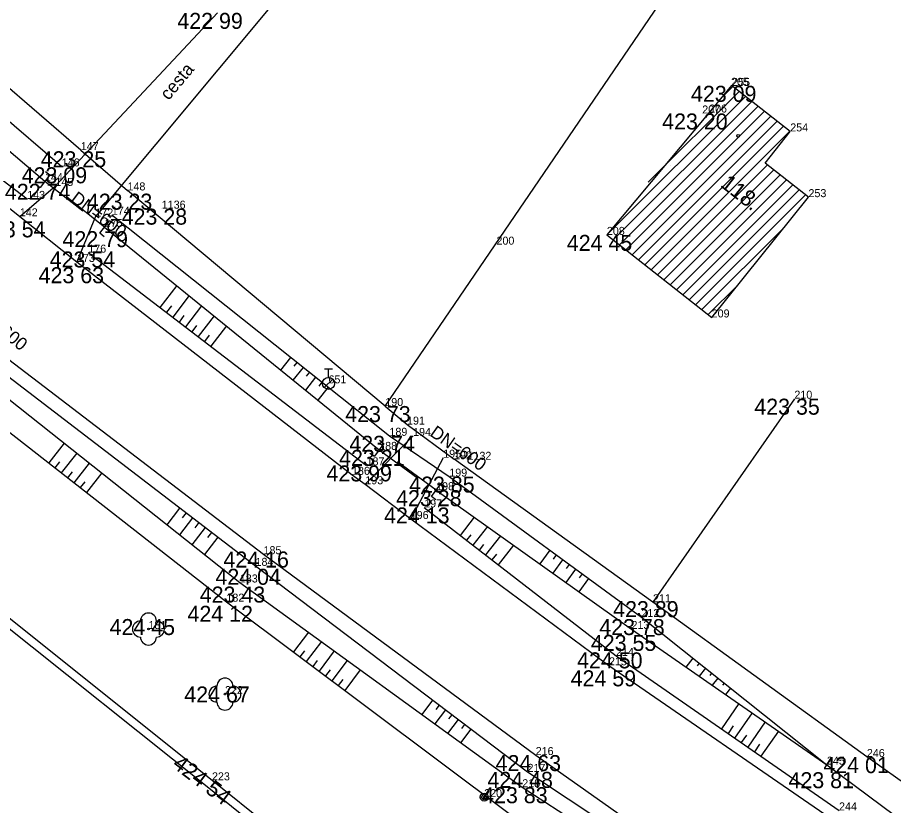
# Model space of a CAD drawing. Extents: x -559180 to -551373, y -1076947 to -1072071.
# Drawn here: x -554542.6 to -554487.8, y -1073678.4 to -1073629.1 of the extents above; entities that cross this region are included whole.
import ezdxf

# ---------------------------------------------------------------- set-up
doc = ezdxf.new("R2010")
doc.units = 0
for name, color, linetype in [('12_PLOTY', 7, 'Continuous'), ('14_BUDOVY', 7, 'Continuous'), ('17_KOMUNIKACE', 7, 'Continuous'), ('1_VODA_ZN', 7, 'Continuous'), ('20_EL_ZN', 7, 'Continuous'), ('26_SRAFY', 7, 'Continuous'), ('27_HRANA_PATA', 7, 'Continuous'), ('32', 7, 'Continuous'), ('34_ZELEN', 7, 'Continuous'), ('3_BODY', 7, 'Continuous'), ('40_KANAL_ZN', 7, 'Continuous'), ('47_ZN_STAV_OBJ$', 7, 'Continuous'), ('49_POPIS_KANAL', 7, 'Continuous'), ('52_POPIS_UCELOVY', 7, 'Continuous'), ('54_C_POPISNA', 7, 'Continuous'), ('6_VYSKY', 7, 'Continuous')]:
    doc.layers.add(name, color=color, linetype=linetype)

# ---------------------------------------------------------------- blocks, each defined once
blk = doc.blocks.new('POINT_DISPLAY')
blk.add_line((0, 0), (0, 0))
blk = doc.blocks.new('BZ')
at = {"layer": '47_ZN_STAV_OBJ$'}
blk.add_circle((0, 0), 0.0875, dxfattribs=at)
blk = doc.blocks.new('JS600')
at = {"layer": '49_POPIS_KANAL'}
blk.add_text('DN=600', height=0.8, rotation=0, dxfattribs=at).set_placement((0.752, -0.172))
blk = doc.blocks.new('STL')
at = {"layer": '34_ZELEN'}
blk.add_circle((0, 0), 0.05, dxfattribs=at)
for centre, start, end in [((0, 0.5), 0, 180), ((-0.5, 0), 90, 270), ((0.5, 0), 270, 90), ((0, -0.5), 180, 0)]:
    blk.add_arc(centre, 0.5, start, end, dxfattribs=at)
blk = doc.blocks.new('SLB')
at = {"layer": '20_EL_ZN'}
for radius in [0.25, 0.158, 0.05]:
    blk.add_circle((0, 0), radius, dxfattribs=at)
blk = doc.blocks.new('VYUST')
at = {"layer": '40_KANAL_ZN'}
for p, q in [((-0.35, 0.5), (0, 0.5)), ((0, 0.5), (0, -0.5)), ((0, 0), (3, 0.001)), ((-0.35, -0.5), (0, -0.5))]:
    blk.add_line(p, q, dxfattribs=at)
blk = doc.blocks.new('HYP')
at = {"layer": '1_VODA_ZN'}
for p, q in [((-0.25, 0.9), (0.25, 0.9)), ((0, 0.375), (0, 0.9)), ((-0.265, -0.265), (0.265, 0.265))]:
    blk.add_line(p, q, dxfattribs=at)
blk.add_circle((0, 0), 0.375, dxfattribs=at)

msp = doc.modelspace()

# ---------------------------------------------------------------- linework, layer by layer
at = {"layer": '12_PLOTY'}
for p, q in [((-554538.64, -1073637.43), (-554551.66, -1073626.19)), ((-554519.61, -1073653.43), (-554502.05, -1073627.66)), ((-554538.64, -1073637.43), (-554535.72, -1073639.95)), ((-554519.61, -1073653.43), (-554535.72, -1073639.95)), ((-554494.04, -1073652.97), (-554502.88, -1073665.7)), ((-554519.61, -1073653.43), (-554518.25, -1073654.59)), ((-554518.25, -1073654.59), (-554515.31, -1073656.76)), ((-554502.88, -1073665.7), (-554515.31, -1073656.76)), ((-554547.942, -1073663.49), (-554530.752, -1073677.22)), ((-554530.44, -1073676.83), (-554547.63, -1073663.1)), ((-554489.51, -1073675.37), (-554502.88, -1073665.7)), ((-554479.77, -1073682.26), (-554489.51, -1073675.37)), ((-554530.752, -1073677.22), (-554503.842, -1073698.76)), ((-554503.53, -1073698.37), (-554530.44, -1073676.83))]:
    msp.add_line(p, q, dxfattribs=at)
at = {"layer": '14_BUDOVY'}
for p, q in [((-554497.978, -1073633.383), (-554499.37, -1073635.08)), ((-554494.3, -1073636.26), (-554497.978, -1073633.383)), ((-554499.37, -1073635.08), (-554505.76, -1073642.73)), ((-554495.862, -1073638.256), (-554494.3, -1073636.26)), ((-554493.16, -1073640.37), (-554495.862, -1073638.256)), ((-554499.21, -1073647.89), (-554493.16, -1073640.37)), ((-554505.76, -1073642.73), (-554499.21, -1073647.89))]:
    msp.add_line(p, q, dxfattribs=at)
at = {"layer": '17_KOMUNIKACE'}
for p, q in [((-554525.78, -1073627.26), (-554537.73, -1073641.58)), ((-554540.23, -1073639.67), (-554530.1, -1073628.85)), ((-554556.69, -1073630.21), (-554542.45, -1073641.57)), ((-554542.45, -1073641.57), (-554540.23, -1073639.67)), ((-554542.45, -1073641.57), (-554538.88, -1073644.42)), ((-554537.73, -1073641.58), (-554538.88, -1073644.42)), ((-554538.88, -1073644.42), (-554521.69, -1073657.73)), ((-554544.29, -1073649.64), (-554527.22, -1073662.69)), ((-554520.86, -1073658.32), (-554517.87, -1073655.3)), ((-554515.99, -1073656.66), (-554518.02, -1073660.49)), ((-554521.69, -1073657.73), (-554520.86, -1073658.32)), ((-554520.86, -1073658.32), (-554518.02, -1073660.49)), ((-554518.02, -1073660.49), (-554505.63, -1073669.64)), ((-554527.22, -1073662.69), (-554510.21, -1073675.25)), ((-554505.63, -1073669.64), (-554491.54, -1073679.37)), ((-554510.21, -1073675.25), (-554496.41, -1073684.98))]:
    msp.add_line(p, q, dxfattribs=at)
at = {"layer": '26_SRAFY'}
for p, q in [((-554532.645, -1073645.898), (-554533.691, -1073647.266)), ((-554531.868, -1073646.528), (-554532.897, -1073647.873)), ((-554532.982, -1073647.162), (-554533.294, -1073647.569)), ((-554531.091, -1073647.159), (-554532.102, -1073648.481)), ((-554532.193, -1073647.777), (-554532.499, -1073648.177)), ((-554530.315, -1073647.789), (-554531.308, -1073649.088)), ((-554531.404, -1073648.391), (-554531.705, -1073648.784)), ((-554529.538, -1073648.42), (-554530.514, -1073649.696)), ((-554530.615, -1073649.006), (-554530.911, -1073649.392)), ((-554526.137, -1073651.18), (-554525.505, -1073650.387)), ((-554525.305, -1073650.937), (-554525.114, -1073650.698)), ((-554525.361, -1073651.81), (-554524.723, -1073651.01)), ((-554524.524, -1073651.563), (-554524.332, -1073651.322)), ((-554524.584, -1073652.441), (-554523.941, -1073651.633)), ((-554523.744, -1073652.188), (-554523.55, -1073651.945)), ((-554523.808, -1073653.071), (-554523.159, -1073652.256)), ((-554539.678, -1073655.749), (-554540.647, -1073656.99)), ((-554538.895, -1073656.371), (-554539.858, -1073657.605)), ((-554539.963, -1073656.926), (-554540.253, -1073657.298)), ((-554538.111, -1073656.992), (-554539.07, -1073658.221)), ((-554539.176, -1073657.543), (-554539.464, -1073657.913)), ((-554537.328, -1073657.614), (-554538.282, -1073658.836)), ((-554538.389, -1073658.161), (-554538.676, -1073658.528)), ((-554533.243, -1073660.855), (-554532.442, -1073659.807)), ((-554532.287, -1073660.427), (-554532.044, -1073660.111)), ((-554532.46, -1073661.476), (-554531.647, -1073660.415)), ((-554531.496, -1073661.039), (-554531.25, -1073660.719)), ((-554514.046, -1073660.385), (-554514.922, -1073661.517)), ((-554531.676, -1073662.098), (-554530.853, -1073661.022)), ((-554530.705, -1073661.651), (-554530.456, -1073661.326)), ((-554513.23, -1073660.965), (-554514.132, -1073662.129)), ((-554530.893, -1073662.72), (-554530.059, -1073661.63)), ((-554514.26, -1073661.479), (-554514.527, -1073661.823)), ((-554512.415, -1073661.545), (-554513.341, -1073662.742)), ((-554513.462, -1073662.081), (-554513.736, -1073662.435)), ((-554511.599, -1073662.125), (-554512.55, -1073663.354)), ((-554512.664, -1073662.684), (-554512.945, -1073663.048)), ((-554509.94, -1073663.304), (-554509.311, -1073662.445)), ((-554509.095, -1073662.996), (-554508.908, -1073662.74)), ((-554509.124, -1073663.883), (-554508.504, -1073663.035)), ((-554508.285, -1073663.583), (-554508.1, -1073663.33)), ((-554508.309, -1073664.463), (-554507.697, -1073663.625)), ((-554507.476, -1073664.17), (-554507.293, -1073663.92)), ((-554507.494, -1073665.042), (-554506.89, -1073664.215)), ((-554524.417, -1073667.566), (-554525.346, -1073668.805)), ((-554523.607, -1073668.154), (-554524.545, -1073669.405)), ((-554524.665, -1073668.732), (-554524.945, -1073669.105)), ((-554522.797, -1073668.741), (-554523.745, -1073670.005)), ((-554523.862, -1073669.328), (-554524.145, -1073669.705)), ((-554521.988, -1073669.328), (-554522.945, -1073670.605)), ((-554500.801, -1073669.744), (-554500.365, -1073669.196)), ((-554500.099, -1073669.664), (-554499.974, -1073669.508)), ((-554523.06, -1073669.924), (-554523.345, -1073670.305)), ((-554521.178, -1073669.915), (-554522.145, -1073671.205)), ((-554499.978, -1073670.316), (-554499.583, -1073669.819)), ((-554522.257, -1073670.52), (-554522.545, -1073670.905)), ((-554499.304, -1073670.272), (-554499.192, -1073670.131)), ((-554499.155, -1073670.887), (-554498.801, -1073670.442)), ((-554498.51, -1073670.88), (-554498.409, -1073670.754)), ((-554498.332, -1073671.459), (-554498.018, -1073671.065)), ((-554517.31, -1073672.72), (-554516.63, -1073671.822)), ((-554516.434, -1073672.391), (-554516.232, -1073672.124)), ((-554497.504, -1073672.034), (-554498.6, -1073673.617)), ((-554516.501, -1073673.307), (-554515.833, -1073672.426)), ((-554515.633, -1073672.99), (-554515.435, -1073672.728)), ((-554496.683, -1073672.605), (-554497.778, -1073674.186)), ((-554515.691, -1073673.894), (-554515.036, -1073673.03)), ((-554514.832, -1073673.589), (-554514.638, -1073673.332)), ((-554495.861, -1073673.175), (-554496.956, -1073674.756)), ((-554514.881, -1073674.481), (-554514.239, -1073673.634)), ((-554497.86, -1073673.427), (-554498.189, -1073673.901)), ((-554495.04, -1073673.746), (-554496.134, -1073675.325)), ((-554497.039, -1073673.997), (-554497.367, -1073674.471)), ((-554496.217, -1073674.567), (-554496.545, -1073675.04))]:
    msp.add_line(p, q, dxfattribs=at)
at = {"layer": '27_HRANA_PATA'}
for p, q in [((-554553.84, -1073626.4), (-554539.83, -1073638.45)), ((-554554.76, -1073627.66), (-554540.88, -1073639.37)), ((-554556.17, -1073629.65), (-554541.99, -1073640.48)), ((-554536.7, -1073641.47), (-554519.35, -1073655.29)), ((-554537.15, -1073642.24), (-554519.99, -1073656.17)), ((-554538.17, -1073643.84), (-554520.78, -1073657.14)), ((-554545.43, -1073649.868), (-554527.72, -1073663.42)), ((-554545.75, -1073650.93), (-554528.7, -1073664.46)), ((-554547.25, -1073651.835), (-554529.54, -1073665.66)), ((-554519.35, -1073655.29), (-554515.61, -1073657.84)), ((-554515.61, -1073657.84), (-554503.6, -1073666.62)), ((-554516.43, -1073658.69), (-554504.22, -1073667.37)), ((-554517.18, -1073659.77), (-554505.19, -1073669.05)), ((-554527.72, -1073663.42), (-554510.72, -1073676.3)), ((-554528.7, -1073664.46), (-554511.05, -1073677.26)), ((-554529.54, -1073665.66), (-554511.79, -1073678.97)), ((-554503.6, -1073666.62), (-554492.01, -1073675.85)), ((-554504.22, -1073667.37), (-554492.01, -1073675.85)), ((-554505.19, -1073669.05), (-554491.25, -1073678.71)), ((-554492.01, -1073675.85), (-554482.51, -1073682.92)), ((-554510.72, -1073676.3), (-554496.84, -1073685.47)), ((-554511.05, -1073677.26), (-554497.4, -1073686.05))]:
    msp.add_line(p, q, dxfattribs=at)
at = {"layer": '32'}
for p, q in [((-554503.175, -1073639.437), (-554497.497, -1073633.76)), ((-554498.666, -1073634.222), (-554497.894, -1073633.449)), ((-554505.76, -1073642.73), (-554497.1, -1073634.07)), ((-554505.364, -1073643.042), (-554496.703, -1073634.38)), ((-554504.969, -1073643.353), (-554496.306, -1073634.69)), ((-554504.573, -1073643.665), (-554495.909, -1073635.001)), ((-554504.178, -1073643.976), (-554495.513, -1073635.311)), ((-554503.782, -1073644.288), (-554495.116, -1073635.621)), ((-554503.387, -1073644.6), (-554494.719, -1073635.932)), ((-554502.991, -1073644.911), (-554494.323, -1073636.242)), ((-554502.596, -1073645.223), (-554495.731, -1073638.358)), ((-554502.2, -1073645.534), (-554495.335, -1073638.669)), ((-554501.805, -1073645.846), (-554494.938, -1073638.979)), ((-554501.409, -1073646.157), (-554494.541, -1073639.289)), ((-554501.014, -1073646.469), (-554494.144, -1073639.6)), ((-554500.618, -1073646.781), (-554493.748, -1073639.91)), ((-554500.223, -1073647.092), (-554493.351, -1073640.221)), ((-554499.827, -1073647.404), (-554494.669, -1073642.245)), ((-554499.432, -1073647.715), (-554497.579, -1073645.863))]:
    msp.add_line(p, q, dxfattribs=at)

# ---------------------------------------------------------------- block references
at = {"layer": '1_VODA_ZN'}
for name, p in [('POINT_DISPLAY', (-554498, -1073633.41)), ('POINT_DISPLAY', (-554497.93, -1073633.42)), ('POINT_DISPLAY', (-554499.8, -1073635.14)), ('POINT_DISPLAY', (-554499.37, -1073635.08)), ('POINT_DISPLAY', (-554494.3, -1073636.26)), ('POINT_DISPLAY', (-554538.64, -1073637.43)), ('POINT_DISPLAY', (-554539.83, -1073638.45)), ('POINT_DISPLAY', (-554540.88, -1073639.37)), ('POINT_DISPLAY', (-554540.23, -1073639.67)), ('POINT_DISPLAY', (-554535.72, -1073639.95)), ('POINT_DISPLAY', (-554541.99, -1073640.48)), ('POINT_DISPLAY', (-554493.16, -1073640.37)), ('POINT_DISPLAY', (-554533.58, -1073641.09)), ('POINT_DISPLAY', (-554542.45, -1073641.57)), ('POINT_DISPLAY', (-554537.73, -1073641.58)), ('POINT_DISPLAY', (-554536.7, -1073641.47)), ('POINT_DISPLAY', (-554537.15, -1073642.24)), ('POINT_DISPLAY', (-554505.76, -1073642.73)), ('POINT_DISPLAY', (-554512.66, -1073643.34)), ('POINT_DISPLAY', (-554538.17, -1073643.84)), ('POINT_DISPLAY', (-554538.88, -1073644.42)), ('POINT_DISPLAY', (-554499.21, -1073647.89)), ('HYP', (-554523.16, -1073652.01)), ('POINT_DISPLAY', (-554523.16, -1073652.01)), ('POINT_DISPLAY', (-554494.04, -1073652.97)), ('POINT_DISPLAY', (-554519.61, -1073653.43)), ('POINT_DISPLAY', (-554518.25, -1073654.59)), ('POINT_DISPLAY', (-554519.35, -1073655.29)), ('POINT_DISPLAY', (-554517.87, -1073655.3)), ('POINT_DISPLAY', (-554519.99, -1073656.17)), ('POINT_DISPLAY', (-554515.99, -1073656.66)), ('POINT_DISPLAY', (-554515.31, -1073656.76)), ('POINT_DISPLAY', (-554514.47, -1073656.79)), ('POINT_DISPLAY', (-554520.78, -1073657.14)), ('POINT_DISPLAY', (-554521.69, -1073657.73)), ('POINT_DISPLAY', (-554515.61, -1073657.84)), ('POINT_DISPLAY', (-554520.86, -1073658.32)), ('POINT_DISPLAY', (-554516.43, -1073658.69)), ('POINT_DISPLAY', (-554517.18, -1073659.77)), ('POINT_DISPLAY', (-554518.02, -1073660.49)), ('POINT_DISPLAY', (-554527.22, -1073662.69)), ('POINT_DISPLAY', (-554527.72, -1073663.42)), ('POINT_DISPLAY', (-554528.7, -1073664.46)), ('POINT_DISPLAY', (-554529.54, -1073665.66)), ('POINT_DISPLAY', (-554502.88, -1073665.7)), ('POINT_DISPLAY', (-554503.6, -1073666.62)), ('POINT_DISPLAY', (-554534.41, -1073667.37)), ('POINT_DISPLAY', (-554504.22, -1073667.37)), ('POINT_DISPLAY', (-554505.19, -1073669.05)), ('POINT_DISPLAY', (-554505.63, -1073669.64)), ('POINT_DISPLAY', (-554529.63, -1073671.44)), ('POINT_DISPLAY', (-554510.21, -1073675.25)), ('POINT_DISPLAY', (-554489.51, -1073675.37)), ('POINT_DISPLAY', (-554492.01, -1073675.85)), ('POINT_DISPLAY', (-554510.72, -1073676.3)), ('POINT_DISPLAY', (-554530.44, -1073676.83)), ('POINT_DISPLAY', (-554511.05, -1073677.26)), ('POINT_DISPLAY', (-554513.43, -1073677.88))]:
    msp.add_blockref(name, p, dxfattribs=at)
at = {"layer": '20_EL_ZN'}
msp.add_blockref('SLB', (-554513.43, -1073677.88), dxfattribs=at)
at = {"layer": '32'}
for p in [(-554501.815, -1073638.385), (-554505.76, -1073642.73)]:
    msp.add_blockref('POINT_DISPLAY', p, dxfattribs=at)
at = {"layer": '34_ZELEN'}
for p in [(-554534.41, -1073667.37), (-554529.63, -1073671.44)]:
    msp.add_blockref('STL', p, dxfattribs=at)
at = {"layer": '40_KANAL_ZN'}
for p, xscale, yscale, rotation in [((-554540.88, -1073639.37), 0.999999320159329, 0.9999993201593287, -38.11928391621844), ((-554537.15, -1073642.24), 1.0000001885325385, 1.0000001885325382, 141.65216076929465), ((-554519.99, -1073656.17), 0.9999985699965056, 0.9999985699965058, -36.17282544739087), ((-554516.43, -1073658.69), 1.0000023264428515, 1.0000023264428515, 143.7866682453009)]:
    msp.add_blockref('VYUST', p, dxfattribs=dict(at, xscale=xscale, yscale=yscale, rotation=rotation))
at = {"layer": '47_ZN_STAV_OBJ$'}
msp.add_blockref('BZ', (-554497.553, -1073636.538), dxfattribs=at)
at = {"layer": '49_POPIS_KANAL'}
for p, xscale, yscale, rotation in [((-554539.829, -1073640.008), 1.0000022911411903, 1.0000022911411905, -36.81685698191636), ((-554545.927, -1073646.917), 0.9999989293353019, 0.9999989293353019, -39.193498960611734), ((-554517.396, -1073654.669), 0.9999979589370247, 0.9999979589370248, -35.32795063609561)]:
    msp.add_blockref('JS600', p, dxfattribs=dict(at, xscale=xscale, yscale=yscale, rotation=rotation))

# ---------------------------------------------------------------- texts
at = {"layer": '3_BODY'}
for s, p in [('205', (-554498, -1073633.41)), ('255', (-554497.93, -1073633.42)), ('207', (-554499.8, -1073635.14)), ('206', (-554499.37, -1073635.08)), ('254', (-554494.3, -1073636.26)), ('147', (-554538.64, -1073637.43)), ('146', (-554539.83, -1073638.45)), ('144', (-554540.88, -1073639.37)), ('145', (-554540.23, -1073639.67)), ('148', (-554535.72, -1073639.95)), ('143', (-554541.99, -1073640.48)), ('253', (-554493.16, -1073640.37)), ('142', (-554542.45, -1073641.57)), ('172', (-554537.73, -1073641.58)), ('174', (-554536.7, -1073641.47)), ('1136', (-554533.58, -1073641.09)), ('175', (-554537.15, -1073642.24)), ('208', (-554505.76, -1073642.73)), ('200', (-554512.66, -1073643.34)), ('176', (-554538.17, -1073643.84)), ('173', (-554538.88, -1073644.42)), ('209', (-554499.21, -1073647.89)), ('651', (-554523.16, -1073652.01)), ('210', (-554494.04, -1073652.97)), ('190', (-554519.61, -1073653.43)), ('191', (-554518.25, -1073654.59)), ('189', (-554519.35, -1073655.29)), ('194', (-554517.87, -1073655.3)), ('188', (-554519.99, -1073656.17)), ('195', (-554515.99, -1073656.66)), ('192', (-554515.31, -1073656.76)), ('1132', (-554514.47, -1073656.79)), ('187', (-554520.78, -1073657.14)), ('186', (-554521.69, -1073657.73)), ('199', (-554515.61, -1073657.84)), ('193', (-554520.86, -1073658.32)), ('198', (-554516.43, -1073658.69)), ('197', (-554517.18, -1073659.77)), ('196', (-554518.02, -1073660.49)), ('185', (-554527.22, -1073662.69)), ('184', (-554527.72, -1073663.42)), ('183', (-554528.7, -1073664.46)), ('182', (-554529.54, -1073665.66)), ('211', (-554502.88, -1073665.7)), ('212', (-554503.6, -1073666.62)), ('181', (-554534.41, -1073667.37)), ('213', (-554504.22, -1073667.37)), ('214', (-554505.19, -1073669.05)), ('215', (-554505.63, -1073669.64)), ('222', (-554529.63, -1073671.44)), ('216', (-554510.21, -1073675.25)), ('246', (-554489.51, -1073675.37)), ('245', (-554492.01, -1073675.85)), ('217', (-554510.72, -1073676.3)), ('223', (-554530.44, -1073676.83)), ('218', (-554511.05, -1073677.26)), ('220', (-554513.43, -1073677.88)), ('244', (-554491.25, -1073678.71))]:
    msp.add_text(s, height=0.5, dxfattribs=at).set_placement(p)
at = {"layer": '52_POPIS_UCELOVY'}
msp.add_text('cesta', height=0.8, rotation=50.1551, dxfattribs=at).set_placement((-554533.15, -1073634.361))
at = {"layer": '54_C_POPISNA'}
msp.add_text('118.', height=1, rotation=321.9615, dxfattribs=at).set_placement((-554498.722, -1073639.669))
at = {"layer": '6_VYSKY'}
for s, p in [('422 99', (-554532.605, -1073629.85)), ('423 09', (-554500.505, -1073634.41)), ('423 20', (-554502.305, -1073636.14)), ('423 25', (-554541.145, -1073638.503)), ('423 09', (-554542.335, -1073639.505)), ('422 74', (-554543.385, -1073640.535)), ('423 23', (-554538.262, -1073641.153)), ('423 28', (-554536.085, -1073642.09)), ('423 54', (-554544.937, -1073642.883)), ('422 79', (-554539.784, -1073643.497)), ('424 45', (-554508.265, -1073643.73)), ('423 54', (-554540.583, -1073644.766)), ('423 63', (-554541.275, -1073645.751)), ('423 35', (-554496.545, -1073653.97)), ('423 73', (-554522.115, -1073654.43)), ('423 74', (-554521.855, -1073656.29)), ('423 21', (-554522.495, -1073657.17)), ('423 99', (-554523.285, -1073658.14)), ('423 85', (-554518.115, -1073658.84)), ('423 28', (-554518.935, -1073659.69)), ('424 13', (-554519.685, -1073660.77)), ('424 16', (-554529.725, -1073663.525)), ('424 04', (-554530.225, -1073664.604)), ('423 43', (-554531.205, -1073665.717)), ('423 89', (-554505.367, -1073666.628)), ('424 12', (-554531.971, -1073666.918)), ('424 45', (-554536.841, -1073667.745)), ('423 78', (-554506.234, -1073667.748)), ('423 55', (-554506.762, -1073668.737)), ('424 50', (-554507.622, -1073669.829)), ('424 59', (-554508.025, -1073670.952)), ('424 67', (-554532.171, -1073671.962)), ('424 63', (-554512.715, -1073676.25)), ('424 01', (-554492.231, -1073676.377)), ('424 48', (-554513.225, -1073677.3)), ('423 81', (-554494.409, -1073677.321)), ('423 83', (-554513.555, -1073678.26))]:
    msp.add_text(s, height=1, dxfattribs=at).set_placement(p)
msp.add_text('424 54', height=1, rotation=322.6555, dxfattribs=at).set_placement((-554532.985, -1073675.962))

doc.saveas('drawing.dxf')
